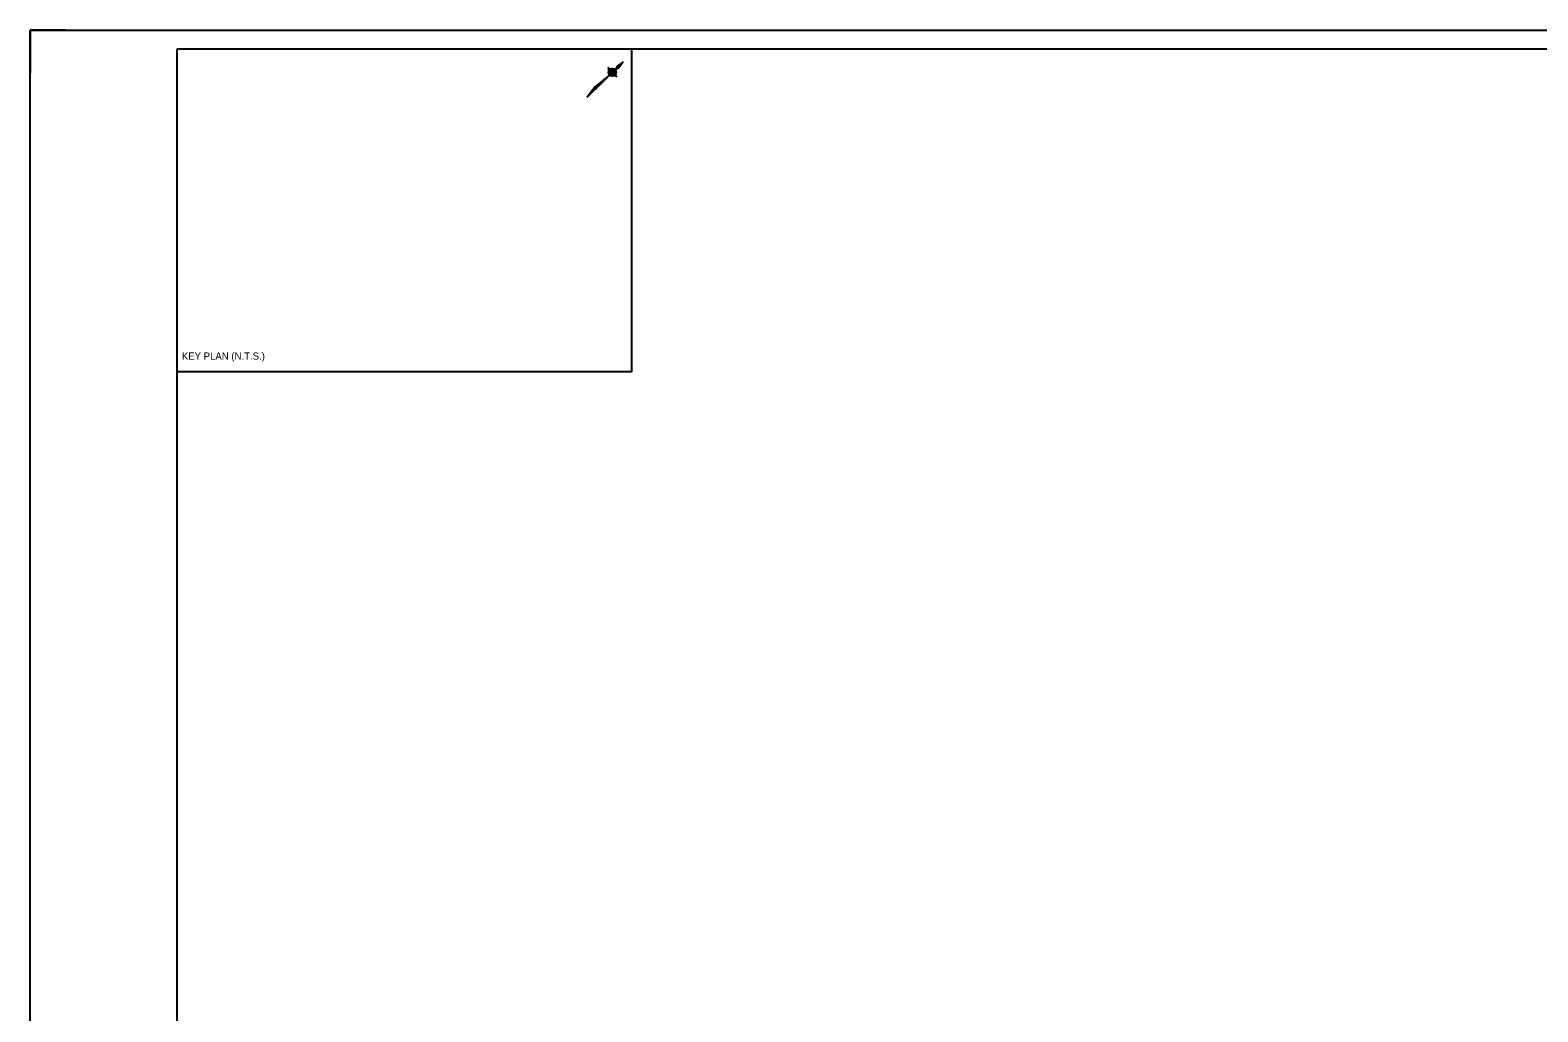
# Model space of a CAD drawing. Extents: x 612883 to 613093, y 4825734 to 4825879.
# Drawn here: x 612882.8 to 612988, y 4825802.1 to 4825870.5 of the extents above; entities that cross this region are included whole.
import ezdxf

# ---------------------------------------------------------------- set-up
doc = ezdxf.new("R2010")
doc.units = 0
for name, color, linetype in [('G-ANNO-KEYP', 7, 'Continuous'), ('G-TTLB-OTLN', 7, 'Continuous'), ('G-TTLB-OTLN-PB', 7, 'Continuous')]:
    doc.layers.add(name, color=color, linetype=linetype)

msp = doc.modelspace()

# ---------------------------------------------------------------- linework, layer by layer
at = {"layer": 'G-ANNO-KEYP'}
for p, q in [((612923.22, 4825867.77), (612923.09, 4825867.9)), ((612923.12, 4825867.81), (612923.19, 4825867.73)), ((612923.18, 4825867.87), (612923.26, 4825867.8)), ((612923.18, 4825867.63), (612923.24, 4825867.68)), ((612923.18, 4825867.61), (612923.23, 4825867.66)), ((612923.18, 4825867.6), (612923.22, 4825867.64)), ((612923.18, 4825867.59), (612923.22, 4825867.63)), ((612923.18, 4825867.58), (612923.21, 4825867.62)), ((612923.18, 4825867.57), (612923.21, 4825867.61)), ((612923.18, 4825867.56), (612923.21, 4825867.59)), ((612923.18, 4825867.55), (612923.21, 4825867.58)), ((612923.18, 4825867.54), (612923.21, 4825867.57)), ((612923.18, 4825867.55), (612923.21, 4825867.57)), ((612923.18, 4825867.53), (612923.21, 4825867.56)), ((612923.18, 4825867.52), (612923.21, 4825867.55)), ((612923.18, 4825867.51), (612923.21, 4825867.54)), ((612923.19, 4825867.65), (612923.34, 4825867.8)), ((612923.19, 4825867.64), (612923.27, 4825867.72)), ((612923.19, 4825867.51), (612923.21, 4825867.53)), ((612923.19, 4825867.49), (612923.22, 4825867.52)), ((612923.19, 4825867.5), (612923.21, 4825867.52)), ((612923.19, 4825867.49), (612923.22, 4825867.51)), ((612923.2, 4825867.67), (612923.33, 4825867.79)), ((612923.2, 4825867.68), (612923.31, 4825867.78)), ((612923.2, 4825867.47), (612923.22, 4825867.5)), ((612923.2, 4825867.48), (612923.22, 4825867.5)), ((612923.2, 4825867.47), (612923.23, 4825867.49)), ((612923.21, 4825867.45), (612923.23, 4825867.48)), ((612923.21, 4825867.46), (612923.23, 4825867.48)), ((612923.21, 4825867.45), (612923.24, 4825867.47)), ((612923.22, 4825867.71), (612923.28, 4825867.77)), ((612923.22, 4825867.44), (612923.24, 4825867.46)), ((612923.22, 4825867.44), (612923.24, 4825867.46)), ((612923.23, 4825867.43), (612923.25, 4825867.45)), ((612923.23, 4825867.43), (612923.25, 4825867.45)), ((612923.23, 4825867.42), (612923.26, 4825867.44)), ((612923.24, 4825867.41), (612923.26, 4825867.44)), ((612923.24, 4825867.41), (612923.27, 4825867.43)), ((612923.25, 4825867.41), (612923.27, 4825867.43)), ((612923.25, 4825867.4), (612923.28, 4825867.42)), ((612923.26, 4825867.4), (612923.28, 4825867.42)), ((612923.26, 4825867.39), (612923.29, 4825867.41)), ((612923.27, 4825867.39), (612923.29, 4825867.41)), ((612923.27, 4825867.38), (612923.3, 4825867.41)), ((612923.28, 4825867.72), (612923.36, 4825867.8)), ((612923.28, 4825867.72), (612923.36, 4825867.8)), ((612923.42, 4825867.7), (612923.28, 4825867.57)), ((612923.28, 4825867.57), (612923.3, 4825867.56)), ((612923.28, 4825867.38), (612923.3, 4825867.4)), ((612923.3, 4825867.56), (612923.39, 4825867.65)), ((612923.31, 4825867.75), (612923.37, 4825867.8)), ((612923.33, 4825867.76), (612923.38, 4825867.81)), ((612923.35, 4825867.77), (612923.39, 4825867.81)), ((612923.36, 4825867.77), (612923.4, 4825867.81)), ((612923.37, 4825867.77), (612923.41, 4825867.81)), ((612923.39, 4825867.78), (612923.42, 4825867.81)), ((612923.39, 4825867.65), (612923.4, 4825867.45)), ((612923.4, 4825867.78), (612923.43, 4825867.81)), ((612923.4, 4825867.45), (612923.53, 4825867.58)), ((612923.41, 4825867.78), (612923.44, 4825867.81)), ((612923.42, 4825867.78), (612923.45, 4825867.81)), ((612923.43, 4825867.51), (612923.42, 4825867.7)), ((612923.43, 4825867.78), (612923.46, 4825867.81)), ((612923.52, 4825867.6), (612923.43, 4825867.51)), ((612923.44, 4825867.77), (612923.47, 4825867.8)), ((612923.44, 4825867.78), (612923.46, 4825867.8)), ((612923.45, 4825867.77), (612923.48, 4825867.8)), ((612923.46, 4825867.77), (612923.49, 4825867.8)), ((612923.47, 4825867.77), (612923.49, 4825867.79)), ((612923.47, 4825867.35), (612923.64, 4825867.51)), ((612923.48, 4825867.76), (612923.51, 4825867.79)), ((612923.48, 4825867.77), (612923.5, 4825867.79)), ((612923.48, 4825867.35), (612923.63, 4825867.5)), ((612923.49, 4825867.76), (612923.51, 4825867.79)), ((612923.5, 4825867.76), (612923.53, 4825867.78)), ((612923.5, 4825867.76), (612923.52, 4825867.78)), ((612923.5, 4825867.36), (612923.63, 4825867.48)), ((612923.5, 4825867.36), (612923.63, 4825867.48)), ((612923.51, 4825867.75), (612923.53, 4825867.78)), ((612923.52, 4825867.75), (612923.54, 4825867.77)), ((612923.52, 4825867.75), (612923.54, 4825867.77)), ((612923.53, 4825867.58), (612923.52, 4825867.6)), ((612923.52, 4825867.36), (612923.62, 4825867.46)), ((612923.53, 4825867.74), (612923.56, 4825867.76)), ((612923.53, 4825867.74), (612923.55, 4825867.76)), ((612923.54, 4825867.73), (612923.56, 4825867.76)), ((612923.54, 4825867.73), (612923.57, 4825867.75)), ((612923.54, 4825867.38), (612923.6, 4825867.44)), ((612923.55, 4825867.72), (612923.57, 4825867.75)), ((612923.55, 4825867.72), (612923.58, 4825867.74)), ((612923.56, 4825867.72), (612923.58, 4825867.74)), ((612923.56, 4825867.71), (612923.59, 4825867.73)), ((612923.57, 4825867.71), (612923.59, 4825867.73)), ((612923.57, 4825867.7), (612923.59, 4825867.72)), ((612923.58, 4825867.69), (612923.6, 4825867.72)), ((612923.58, 4825867.69), (612923.6, 4825867.71)), ((612923.58, 4825867.68), (612923.61, 4825867.71)), ((612923.58, 4825867.47), (612923.64, 4825867.52)), ((612923.59, 4825867.68), (612923.61, 4825867.7)), ((612923.59, 4825867.67), (612923.61, 4825867.69)), ((612923.59, 4825867.66), (612923.62, 4825867.69)), ((612923.6, 4825867.66), (612923.62, 4825867.68)), ((612923.6, 4825867.65), (612923.62, 4825867.68)), ((612923.6, 4825867.64), (612923.63, 4825867.67)), ((612923.6, 4825867.5), (612923.65, 4825867.54)), ((612923.6, 4825867.49), (612923.64, 4825867.53)), ((612923.61, 4825867.64), (612923.63, 4825867.66)), ((612923.61, 4825867.63), (612923.63, 4825867.66)), ((612923.61, 4825867.62), (612923.64, 4825867.65)), ((612923.61, 4825867.62), (612923.64, 4825867.64)), ((612923.61, 4825867.61), (612923.64, 4825867.63)), ((612923.61, 4825867.6), (612923.64, 4825867.63)), ((612923.61, 4825867.59), (612923.64, 4825867.62)), ((612923.61, 4825867.56), (612923.65, 4825867.59)), ((612923.61, 4825867.55), (612923.65, 4825867.58)), ((612923.61, 4825867.54), (612923.65, 4825867.57)), ((612923.61, 4825867.53), (612923.65, 4825867.56)), ((612923.61, 4825867.52), (612923.65, 4825867.55)), ((612923.62, 4825867.58), (612923.64, 4825867.61)), ((612923.62, 4825867.57), (612923.65, 4825867.6)), ((612923.71, 4825867.34), (612923.63, 4825867.42)), ((612924.15, 4825868.29), (612923.65, 4825867.81)), ((612923.74, 4825868), (612923.65, 4825867.81)), ((612923.85, 4825867.89), (612923.65, 4825867.81)), ((612923.66, 4825867.81), (612924.12, 4825868.26)), ((612923.68, 4825867.82), (612924.1, 4825868.23)), ((612923.69, 4825867.83), (612924.07, 4825868.2)), ((612923.71, 4825867.83), (612924.05, 4825868.16)), ((612923.73, 4825867.84), (612924.02, 4825868.13)), ((612924.15, 4825868.29), (612923.74, 4825868)), ((612923.74, 4825867.85), (612924, 4825868.09)), ((612923.76, 4825867.86), (612923.97, 4825868.06)), ((612923.78, 4825867.86), (612923.95, 4825868.03)), ((612923.79, 4825867.87), (612923.92, 4825867.99)), ((612923.81, 4825867.88), (612923.9, 4825867.96)), ((612923.83, 4825867.88), (612923.87, 4825867.92)), ((612924.15, 4825868.29), (612923.85, 4825867.89)), ((612923.22, 4825867.38), (612921.66, 4825865.85)), ((612922.21, 4825866.56), (612921.66, 4825865.85)), ((612921.68, 4825865.88), (612922.39, 4825866.57)), ((612921.71, 4825865.92), (612923.21, 4825867.38)), ((612921.74, 4825865.96), (612923.15, 4825867.33)), ((612921.77, 4825866), (612923.09, 4825867.28)), ((612921.8, 4825866.04), (612923.03, 4825867.23)), ((612921.83, 4825866.07), (612922.97, 4825867.18)), ((612921.86, 4825866.11), (612922.91, 4825867.14)), ((612921.89, 4825866.15), (612922.85, 4825867.09)), ((612921.92, 4825866.19), (612922.79, 4825867.04)), ((612921.95, 4825866.23), (612922.73, 4825866.99)), ((612921.97, 4825866.26), (612922.67, 4825866.94)), ((612922, 4825866.3), (612922.61, 4825866.89)), ((612922.03, 4825866.34), (612922.55, 4825866.85)), ((612922.06, 4825866.38), (612922.49, 4825866.8)), ((612922.09, 4825866.42), (612922.44, 4825866.75)), ((612922.12, 4825866.45), (612922.38, 4825866.7)), ((612922.15, 4825866.49), (612922.32, 4825866.65)), ((612922.18, 4825866.53), (612922.26, 4825866.6)), ((612923.22, 4825867.38), (612922.21, 4825866.56)), ((612923.29, 4825867.38), (612923.31, 4825867.4)), ((612923.29, 4825867.37), (612923.32, 4825867.39)), ((612923.3, 4825867.37), (612923.32, 4825867.39)), ((612923.3, 4825867.36), (612923.33, 4825867.39)), ((612923.31, 4825867.36), (612923.34, 4825867.39)), ((612923.32, 4825867.36), (612923.34, 4825867.38)), ((612923.32, 4825867.36), (612923.35, 4825867.38)), ((612923.33, 4825867.35), (612923.36, 4825867.38)), ((612923.34, 4825867.35), (612923.36, 4825867.38)), ((612923.35, 4825867.35), (612923.37, 4825867.37)), ((612923.35, 4825867.35), (612923.38, 4825867.37)), ((612923.36, 4825867.34), (612923.39, 4825867.37)), ((612923.37, 4825867.34), (612923.4, 4825867.37)), ((612923.38, 4825867.34), (612923.41, 4825867.37)), ((612923.39, 4825867.34), (612923.42, 4825867.37)), ((612923.4, 4825867.34), (612923.43, 4825867.37)), ((612923.4, 4825867.34), (612923.44, 4825867.37)), ((612923.41, 4825867.34), (612923.45, 4825867.37)), ((612923.42, 4825867.34), (612923.46, 4825867.38)), ((612923.43, 4825867.34), (612923.48, 4825867.38)), ((612923.45, 4825867.34), (612923.49, 4825867.39)), ((612923.46, 4825867.34), (612923.51, 4825867.4)), ((612923.64, 4825867.27), (612923.57, 4825867.35)), ((612923.6, 4825867.38), (612923.73, 4825867.25))]:
    msp.add_line(p, q, dxfattribs=at)
for points in [[(612923.65, 4825867.81), (612923.85, 4825867.89), (612924.15, 4825868.29)], [(612921.66, 4825865.85), (612923.22, 4825867.38), (612922.21, 4825866.56)]]:
    msp.add_lwpolyline(points, close=True, dxfattribs=at)
for radius in [0.271, 0.235, 0.203, 0.174]:
    msp.add_circle((612923.41, 4825867.57), radius, dxfattribs=at)
at = {"layer": 'G-TTLB-OTLN'}
for points in [[(612893.05, 4825869.21), (613090.1, 4825869.21), (613090.1, 4825734.93), (612893.05, 4825734.93)], [(612893.05, 4825869.21), (612924.75, 4825869.21), (612924.75, 4825846.69), (612893.05, 4825846.69)]]:
    msp.add_lwpolyline(points, close=True, dxfattribs=at)
at = {"layer": 'G-TTLB-OTLN-PB'}
for p, q in [((612885.3, 4825870.51), (612882.8, 4825870.51)), ((612882.8, 4825870.51), (612882.8, 4825867.51))]:
    msp.add_line(p, q, dxfattribs=at)
msp.add_lwpolyline([(612882.8, 4825870.51), (613093.15, 4825870.51), (613093.15, 4825733.63), (612882.8, 4825733.63)], close=True, dxfattribs=at)

# ---------------------------------------------------------------- texts
at = {"layer": 'G-ANNO-KEYP'}
msp.add_text('KEY PLAN (N.T.S.)', height=0.5, rotation=359.9998, dxfattribs=at).set_placement((612893.38, 4825847.54))

doc.saveas('drawing.dxf')
